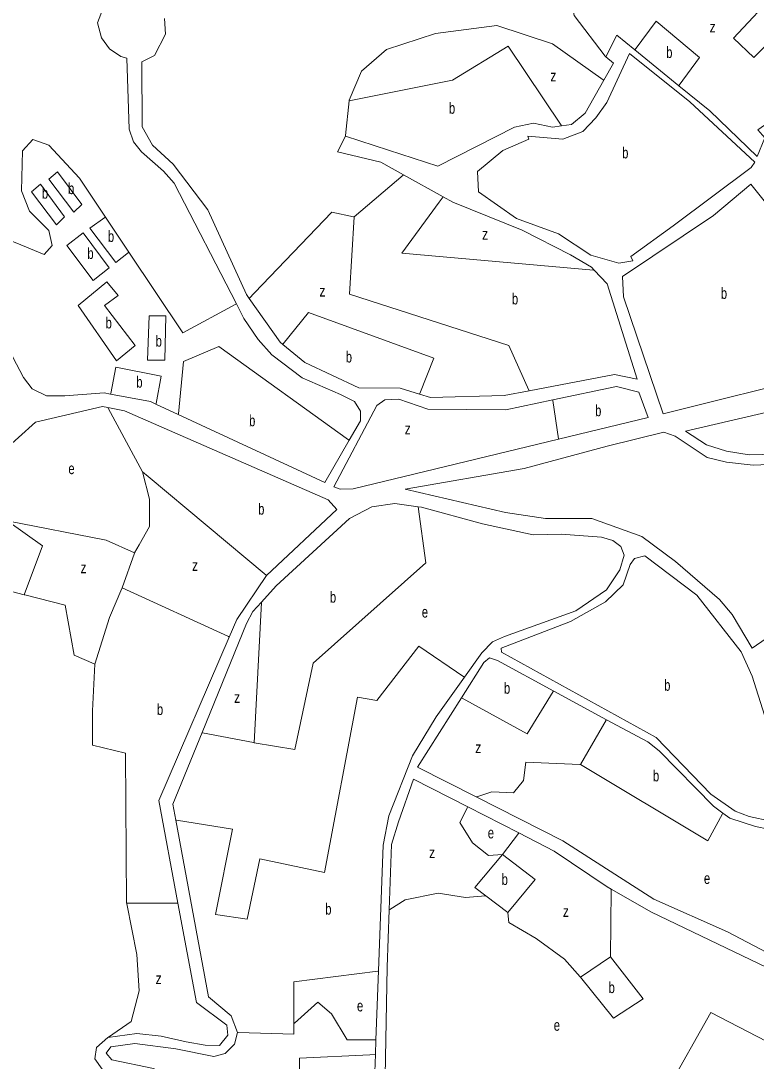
# Model space of a CAD drawing. Extents: x 639657 to 671642, y 222838 to 252123.
# Drawn here: x 644289 to 644946, y 240211 to 241140 of the extents above; entities that cross this region are included whole.
import ezdxf

# ---------------------------------------------------------------- set-up
doc = ezdxf.new("R2010")
doc.units = 0
doc.header["$LTSCALE"] = 4
doc.layers.add('1', color=7, linetype='Continuous', lineweight=13)
doc.layers.add('21', color=7, linetype='Continuous', lineweight=13)
doc.layers.add('7', color=7, linetype='Continuous')

msp = doc.modelspace()

# ---------------------------------------------------------------- linework, layer by layer
at = {"layer": '1'}
for p, q in [((644617.58, 241024.14), (644579.193, 241036.805)), ((644426.28, 240994.63), (644481.637, 240887.039)), ((644356.66, 240223.3), (644366.95, 240232.13))]:
    msp.add_line(p, q, dxfattribs=at)
for points in [[(644328.766, 241279.423), (644347.01, 241274.33), (644376.89, 241255.27), (644369.89, 241200.06), (644374.24, 241169.79), (644363.53, 241153.23), (644357.54, 241137.76), (644361.21, 241124.45), (644368.31, 241114.59), (644378.42, 241107.73), (644384, 241106.45), (644385.83, 241042.88), (644389.71, 241031.72), (644397.03, 241022.71), (644416.6, 241005.35), (644426.28, 240994.63)], [(644417.45, 241141.72), (644418.33, 241127.77), (644408.48, 241108.64), (644397.32, 241103.03), (644397.63, 241045.05), (644406.9, 241028.53), (644425.39, 241011.81), (644456.17, 240971.05), (644490.65, 240895.3), (644493.175, 240891.741)], [(644811.38, 241107.57), (644821.38, 241126.8), (644837.462, 241113.717), (644876.758, 241081.749)], [(644809.73, 241086.776), (644818.26, 241102), (644811.38, 241107.57)], [(644771.858, 241045.898), (644780.77, 241047.17), (644793.21, 241057.29), (644809.73, 241086.776)], [(644876.758, 241081.749), (644904.23, 241059.4), (644946.611, 241018.583), (644953.45, 241035.21), (644947.22, 241042.29), (644993.68, 241074.72)], [(644617.58, 241024.14), (644661.63, 241009.83), (644730.09, 241044.73), (644746.83, 241048.41), (644764.02, 241044.78), (644771.858, 241045.898)], [(644579.193, 241036.805), (644572.083, 241022.58), (644610.645, 241013.42)], [(644801.038, 240917.032), (644798.58, 240919.63), (644780.1, 240930.77), (644736.89, 240952.82), (644675, 240977.85), (644666.285, 240982.667), (644630.948, 241002.198), (644610.645, 241013.42)], [(644742.975, 240809.499), (644819.14, 240824.1), (644839.55, 240819.83), (644812.57, 240904.84), (644801.038, 240917.032)], [(644369.439, 240806.395), (644363.66, 240807.47), (644328.44, 240805.05), (644312.12, 240805.02), (644299.44, 240811.23), (644291.69, 240821.31), (644281.99, 240839.33), (644275.76, 240846.41), (644265.65, 240851.33), (644215.35, 240880.46), (644188.516, 240903.29)], [(644481.637, 240887.039), (644488.33, 240874.03), (644501.24, 240855.15), (644513.29, 240841.64), (644540.38, 240820.85), (644574.77, 240806.09), (644587.24, 240799.88), (644592.4, 240791.09), (644592.42, 240782.71), (644582.352, 240765.348)], [(644493.175, 240891.741), (644520.79, 240852.82), (644523.189, 240850.827)], [(644523.189, 240850.827), (644542.72, 240834.6), (644590.87, 240812.13), (644628.02, 240811.76), (644645.241, 240806.419)], [(644764.066, 240801.24), (644821.09, 240813.36), (644841.07, 240808.24), (644849.27, 240785.49), (644769.259, 240766.18)], [(644409.915, 240797.476), (644404.9, 240799.8), (644369.439, 240806.395)], [(644607.21, 240796.27), (644614.08, 240801.43), (644626.75, 240801.88), (644652.75, 240793.12), (644722.33, 240792.37), (644764.066, 240801.24)], [(644645.241, 240806.419), (644654.88, 240803.43), (644720.81, 240805.25), (644742.975, 240809.499)], [(644366.922, 240794.455), (644362.17, 240795.44), (644302.28, 240781.38), (644241.437, 240726.53)], [(644508.67, 240644.48), (644571.5, 240703.43), (644563.75, 240712.22), (644381.72, 240791.39), (644366.922, 240794.455)], [(644582.352, 240765.348), (644560.51, 240727.68), (644429.845, 240788.239), (644409.915, 240797.476)], [(644769.259, 240766.18), (644585.86, 240721.92), (644574.48, 240721.47), (644568.67, 240723.83), (644607.21, 240796.27)], [(645121.99, 240708.78), (645115.27, 240725.93), (645093.96, 240740.23), (645047.48, 240754.87), (644939.52, 240752.35), (644919.12, 240755.53), (644901.5, 240761.09), (644882.79, 240773.52), (644963.16, 240792.22)], [(645000.69, 240620.15), (644942.17, 240579.68), (644924.29, 240609.72), (644913.1, 240623.23), (644873.75, 240657.1), (644843.64, 240679.39), (644798.95, 240695.42), (644757.71, 240695.36), (644722.05, 240700.88), (644632.46, 240721.57), (644738.53, 240739.99), (644812.8, 240760.09), (644863.25, 240772.63), (644873.56, 240768.99), (644901.94, 240749.92), (644919.13, 240745.66), (644943.19, 240742.9), (645038.84, 240747.12)], [(644643.965, 240705.87), (644623.03, 240708.67), (644602.64, 240705.84), (644582.68, 240695.5), (644517.06, 240635.26), (644504.041, 240620.836)], [(644685.226, 240553.79), (644700.78, 240575.64), (644710.43, 240585.32), (644721.16, 240590.06), (644784.69, 240612.93), (644812.15, 240631.87), (644824.15, 240649.5), (644827.78, 240662.61), (644824.97, 240670.34), (644817.66, 240675.91), (644807.78, 240678.68), (644771.69, 240681.42), (644746.57, 240680.95), (644701.45, 240690.75), (644646.88, 240705.48), (644643.965, 240705.87)], [(644475.311, 240589.62), (644482.1, 240605.35), (644508.67, 240644.48)], [(644504.041, 240620.836), (644496.48, 240612.46), (644490.7, 240601.72), (644451.003, 240504.287)], [(644429.552, 240351.953), (644412.35, 240443.74), (644475.311, 240589.62)], [(644682.71, 240535.362), (644702.73, 240566.84), (644707.66, 240570.93), (644714.75, 240568.58), (644764.958, 240541.408), (644812.198, 240515.842)], [(644608.517, 240291.558), (644612.58, 240403.69), (644617.9, 240429.9), (644638.86, 240483.62), (644660.07, 240518.45), (644685.226, 240553.79)], [(644695.876, 240446.922), (644643.39, 240473.54), (644682.71, 240535.362)], [(644812.198, 240515.842), (644848.88, 240495.99), (644859.2, 240488.06), (644907.6, 240438.53), (644916.081, 240432.439)], [(644451.003, 240504.287), (644425.03, 240440.54), (644427.683, 240426.218), (644456.88, 240268.56)], [(644618.23, 240346.071), (644620.31, 240404.34), (644626.29, 240424.76), (644639.75, 240462.79), (644688.226, 240438.032), (644733.932, 240414.688)], [(645002.394, 240336.638), (645003.71, 240309.61), (645008.09, 240289.02), (645013.71, 240277.44), (644920.24, 240326.44), (644854.26, 240355.54), (644773, 240407.81), (644695.876, 240446.922)], [(644916.081, 240432.439), (644922.22, 240428.03), (644945, 240420.55), (644980.02, 240413.3), (644986.47, 240408.16), (644993.221, 240381.345), (644999.44, 240356.64)], [(644733.932, 240414.688), (644765.49, 240398.57), (644812.58, 240366.64), (644816.431, 240364.442)], [(644816.431, 240364.442), (644852.35, 240343.94), (644999.77, 240273.31)], [(644366.95, 240232.13), (644392.93, 240235.6), (644414.63, 240233.28), (644436.97, 240228.16), (644453.72, 240225.39), (644466.61, 240224.98), (644473.9, 240234.23), (644473.03, 240243.03), (644446.15, 240263.39), (644429.552, 240351.953)], [(644874.32, 239942.39), (644820.41, 239954.54), (644772.32, 239988.98), (644678.8, 240092.17), (644668.69, 240099.46), (644661.6, 240099.45), (644655.16, 240097.29), (644648.3, 240093.41), (644627.93, 240074.91), (644623.63, 240077.7), (644625.96, 240096.17), (644614.22, 240181.63), (644616.4, 240294.81), (644618.23, 240346.071)], [(644487.093, 240136.453), (644495.12, 240123.88), (644500.74, 240106.7), (644506.77, 240091.9), (644520.74, 240088.7), (644534.05, 240090.01), (644549.31, 240084.45), (644578.32, 240069.68), (644596.8, 240066.48), (644608.82, 240067.79), (644615.25, 240080.04), (644616.29, 240099.8), (644610.65, 240136.52), (644604.97, 240193.64), (644605.811, 240216.845), (644606.288, 240230.021), (644608.517, 240291.558)], [(644456.88, 240268.56), (644476.88, 240251.42), (644482.7, 240236.61)], [(644482.7, 240236.61), (644480.14, 240226.29), (644471.78, 240217.9), (644461.47, 240215.1), (644427.53, 240222.13), (644391.01, 240226.79), (644369.54, 240223.75), (644365.47, 240218.16), (644370.63, 240212.16), (644407.8, 240204.49), (644427.79, 240195.07), (644448, 240177.49), (644481.56, 240145.12), (644487.093, 240136.453)], [(644361.84, 240203.98), (644355.38, 240213.21), (644356.66, 240223.3)]]:
    msp.add_lwpolyline(points, dxfattribs=at)
for points in [[(644941.28, 241008.63), (644871.76, 240956.69), (644833.79, 240929.35), (644835.73, 240925.28), (644823.06, 240923.32), (644798.14, 240930.59), (644769.33, 240949.65), (644731.72, 240963.12), (644697.75, 240987.12), (644696.86, 241005.16), (644719.6, 241023.88), (644742.77, 241034.01), (644741.91, 241036.8), (644773.27, 241034.06), (644790.87, 241040.75), (644802.45, 241053.22), (644812.3, 241066.77), (644832.64, 241110.4), (644886.61, 241067.32), (644944.68, 241013.51)], [(645003.46, 240823.98), (645024.03, 240834), (644976.61, 240949.11), (644940.85, 240993.96), (644907.61, 240965.77), (644826.52, 240911.3), (644827.4, 240893.26), (644862.79, 240788.95)], [(644846.46, 240662.21), (644892.69, 240626.85), (644932.29, 240576.44), (644942.21, 240554.77), (644982.57, 240426.62), (644983.01, 240422.97), (644978.07, 240421.03), (644939.62, 240429.34), (644926.94, 240434.05), (644905.22, 240449.26), (644856.39, 240499.87), (644718.39, 240576.1), (644717.95, 240579.75), (644779.98, 240603.47), (644811.09, 240621.13), (644826.96, 240636.19), (644833.37, 240654.24), (644837.02, 240659.83)]]:
    msp.add_lwpolyline(points, close=True, dxfattribs=at)
at = {"layer": '21'}
for p, q in [((644344.855, 240950.411), (644368.211, 240919.256)), ((644350.893, 240954.551), (644373.943, 240923.803)), ((644815.572, 240304.002), (644788.919, 240285.907))]:
    msp.add_line(p, q, dxfattribs=at)
for points in [[(645012.85, 241169.32), (645012.35, 241169.607), (644957.006, 241201.414), (644905.209, 241161.786), (644836.146, 241200.398), (644819.896, 241180.076), (644804.662, 241183.124), (644785.365, 241183.124), (644778.256, 241172.963), (644783.334, 241144.512), (644811, 241108.07), (644811.38, 241107.57)], [(644250.13, 241164.834), (644232.864, 241132.318), (644217.63, 241096.755), (644211.536, 241080.497), (644226.77, 241071.352), (644225.755, 241025.628), (644216.614, 241024.612), (644223.723, 240952.468), (644236.926, 240955.517), (644261.301, 240950.436), (644285.676, 240941.291), (644310.052, 240931.13), (644317.161, 240939.259), (644314.114, 240952.468), (644296.848, 240969.742), (644289.739, 240988.032), (644290.755, 241023.596), (644299.895, 241033.757), (644314.114, 241028.676), (644341.536, 240999.209), (644364.861, 240964.333), (644385.719, 240933.147)], [(644582.24, 241068.304), (644582.451, 241068.804), (644593.412, 241094.723), (644615.755, 241114.029), (644659.427, 241128.254), (644714.271, 241135.367), (644764.037, 241119.11), (644809.23, 241087.13), (644809.73, 241086.776)], [(644837.462, 241113.717), (644837.831, 241114.217), (644856.459, 241139.432), (644895.053, 241106.916), (644877.121, 241082.249), (644876.758, 241081.749)], [(644582.24, 241068.304), (644674.662, 241086.594), (644724.427, 241117.077), (644771.525, 241046.398), (644771.858, 241045.898)], [(644579.193, 241036.805), (644579.241, 241037.305), (644582.24, 241068.304)], [(644586.809, 240964.662), (644630.448, 241001.773), (644630.948, 241002.198)], [(644666.285, 240982.667), (644662.641, 240977.667), (644629.465, 240932.147), (644800.537, 240917.076), (644801.038, 240917.032)], [(644586.809, 240964.662), (644586.309, 240964.765), (644567.005, 240968.727), (644497.97, 240896.741), (644493.175, 240891.741)], [(644350.893, 240954.551), (644364.361, 240963.983), (644364.861, 240964.333)], [(644742.975, 240809.499), (644742.751, 240809.999), (644724.934, 240849.843), (644582.747, 240895.567), (644586.809, 240964.662)], [(644344.855, 240950.411), (644330.364, 240939.259), (644353.723, 240907.76), (644368.211, 240919.256)], [(644373.943, 240923.803), (644385.219, 240932.75), (644385.719, 240933.147)], [(644385.719, 240933.147), (644433.958, 240861.019), (644481.137, 240886.766), (644481.637, 240887.039)], [(644523.189, 240850.827), (644523.593, 240851.327), (644546.184, 240879.31), (644657.903, 240838.666), (644645.437, 240806.919), (644645.241, 240806.419)], [(644582.352, 240765.348), (644581.852, 240765.707), (644465.95, 240848.827), (644434.465, 240835.617), (644429.894, 240788.739), (644429.845, 240788.239)], [(644369.439, 240806.395), (644369.534, 240806.895), (644374.036, 240830.536), (644414.661, 240822.408), (644410.01, 240797.976), (644409.915, 240797.476)], [(644764.066, 240801.24), (644764.14, 240800.74), (644769.185, 240766.68), (644769.259, 240766.18)], [(644397.903, 240737.055), (644367.192, 240793.956), (644366.922, 240794.455)], [(644390.793, 240664.912), (644394.856, 240672.025), (644403.996, 240688.283), (644403.996, 240712.669), (644397.903, 240737.055)], [(644397.903, 240737.055), (644402.903, 240732.876), (644508.17, 240644.903), (644508.67, 240644.48)], [(644643.965, 240705.87), (644643.977, 240705.782), (644650.793, 240655.768), (644550.246, 240566.351), (644533.996, 240489.127), (644497.434, 240495.224)], [(644277.043, 240693.363), (644277.543, 240693.008), (644308.527, 240671.009), (644292.277, 240627.317), (644254.901, 240637.179)], [(644277.043, 240693.363), (644365.403, 240676.089), (644390.793, 240664.912)], [(644379.621, 240633.413), (644390.616, 240664.412), (644390.793, 240664.912)], [(644379.621, 240633.413), (644379.41, 240632.913), (644368.449, 240606.995), (644355.246, 240565.334)], [(644475.311, 240589.62), (644474.59, 240589.95), (644379.621, 240633.413)], [(644355.246, 240565.334), (644354.746, 240565.556), (644336.965, 240573.463), (644328.84, 240618.172), (644292.777, 240627.192), (644292.277, 240627.317)], [(644497.434, 240495.224), (644504.015, 240620.337), (644504.041, 240620.836)], [(644427.683, 240426.218), (644428.182, 240426.137), (644478.137, 240418), (644462.902, 240341.792), (644491.34, 240337.728), (644502.512, 240391.581), (644560.403, 240379.388), (644589.856, 240535.868), (644607.121, 240532.819), (644644.7, 240581.592), (644684.726, 240554.133), (644685.226, 240553.79)], [(644355.246, 240565.334), (644353.215, 240523.674), (644353.215, 240493.191), (644382.668, 240486.078), (644383.684, 240351.953)], [(644764.958, 240541.408), (644764.646, 240540.908), (644741.184, 240503.352), (644683.21, 240535.088), (644682.71, 240535.362)], [(644812.198, 240515.842), (644811.906, 240515.342), (644788.919, 240475.918)], [(644497.434, 240495.224), (644496.934, 240495.322), (644451.503, 240504.189), (644451.003, 240504.287)], [(644695.876, 240446.922), (644696.377, 240447.089), (644709.7, 240451.531), (644728.997, 240450.515), (644738.137, 240461.692), (644740.168, 240477.95), (644788.419, 240475.939), (644788.919, 240475.918)], [(644788.919, 240475.918), (644902.669, 240407.839), (644915.808, 240431.939), (644916.081, 240432.439)], [(644719.332, 240395.58), (644706.653, 240394.63), (644692.434, 240405.807), (644681.262, 240424.097), (644687.976, 240437.532), (644688.226, 240438.032)], [(644719.332, 240395.58), (644733.55, 240414.188), (644733.932, 240414.688)], [(644719.332, 240395.58), (644694.465, 240366.179), (644704.519, 240358.549), (644723.918, 240343.825)], [(644723.918, 240343.825), (644748.293, 240373.291), (644719.332, 240395.58)], [(644815.572, 240304.002), (644816.418, 240363.533), (644816.431, 240364.442)], [(644704.519, 240358.549), (644704.018, 240358.507), (644686.34, 240357.034), (644661.965, 240361.098), (644632.512, 240355.002), (644618.73, 240346.384), (644618.23, 240346.071)], [(644383.684, 240351.953), (644383.784, 240351.453), (644392.824, 240306.229), (644394.856, 240273.713), (644387.746, 240246.279), (644367.45, 240232.47), (644366.95, 240232.13)], [(644383.684, 240351.953), (644429.052, 240351.953), (644429.552, 240351.953)], [(644788.919, 240285.907), (644788.482, 240286.407), (644774.7, 240302.164), (644749.309, 240320.454), (644724.934, 240334.68), (644723.974, 240343.325), (644723.918, 240343.825)], [(644788.919, 240285.907), (644818.372, 240249.327), (644844.778, 240266.601), (644815.572, 240304.002)], [(644532.981, 240244.585), (644532.981, 240281.842), (644608.018, 240291.494), (644608.517, 240291.558)], [(644532.981, 240244.585), (644533.481, 240245.03), (644554.309, 240263.553), (644566.496, 240253.392), (644580.715, 240230.021), (644605.788, 240230.021), (644606.288, 240230.021)], [(645054.47, 240177.13), (645053.97, 240177.389), (644905.208, 240254.407), (644865.598, 240184.296), (644913.333, 240157.878), (644896.067, 240127.395), (644950.911, 240099.96), (644943.801, 240085.734), (645027.083, 240044.074), (645034.192, 240060.332), (645102.052, 240024.264), (645102.552, 240023.998)], [(644482.7, 240236.61), (644483.2, 240236.595), (644532.981, 240235.102), (644532.981, 240244.585)], [(644605.811, 240216.845), (644600.811, 240216.618), (644538.059, 240213.764), (644538.059, 240183.281), (644492.093, 240141.047), (644487.093, 240136.453)]]:
    msp.add_lwpolyline(points, dxfattribs=at)
for points in [[(644994.487, 241102.948), (645012.865, 241123.174), (644965.131, 241166.866), (644925.521, 241124.19), (644943.803, 241106.916), (644967.162, 241130.287)], [(644322.006, 241004.962), (644343.567, 240975.839), (644336.458, 240968.726), (644314.114, 240998.193)], [(644306.772, 240993.785), (644328.333, 240964.662), (644321.224, 240957.549), (644298.88, 240987.016)], [(644374.575, 240836.061), (644391.302, 240849.842), (644363.88, 240885.406), (644376.067, 240894.551), (644365.911, 240906.744), (644340.52, 240885.406)], [(644403.711, 240876.261), (644418.724, 240876.261), (644417.708, 240836.633), (644402.474, 240836.633)]]:
    msp.add_lwpolyline(points, close=True, dxfattribs=at)

# ---------------------------------------------------------------- texts
at = {"layer": '7'}
for s, width, p in [('z', 0.8, (644904.192, 241129.27)), ('b', 0.75, (644865.389, 241106.524)), ('z', 0.8, (644762.005, 241085.578)), ('b', 0.75, (644671.404, 241056.735)), ('b', 0.75, (644826.069, 241016.86)), ('b', 0.75, (644331.38, 240984.984)), ('b', 0.75, (644308.02, 240980.919)), ('b', 0.75, (644366.927, 240942.307)), ('z', 0.8, (644701.067, 240944.34)), ('b', 0.75, (644348.645, 240927.066)), ('z', 0.8, (644555.833, 240893.535)), ('b', 0.75, (644727.632, 240886.51)), ('b', 0.75, (644914.187, 240891.455)), ('b', 0.75, (644364.895, 240865.084)), ('b', 0.75, (644409.583, 240848.826)), ('b', 0.75, (644579.351, 240834.689)), ('b', 0.75, (644392.317, 240812.247)), ('b', 0.75, (644801.945, 240786.721)), ('b', 0.75, (644493.023, 240777.787)), ('z', 0.8, (644632.005, 240770.587)), ('e', 0.75, (644331.681, 240735.035)), ('b', 0.75, (644501.1, 240698.849)), ('z', 0.8, (644342.552, 240646.621)), ('z', 0.8, (644442.083, 240648.653)), ('b', 0.75, (644565.132, 240620.292)), ('e', 0.75, (644647.238, 240606.995)), ('b', 0.75, (644863.581, 240541.62)), ('b', 0.75, (644720.523, 240539.004)), ('z', 0.8, (644479.661, 240530.786)), ('b', 0.75, (644410.709, 240520.016)), ('z', 0.8, (644694.973, 240486.078)), ('b', 0.75, (644853.57, 240460.764)), ('e', 0.75, (644706.145, 240409.871)), ('z', 0.8, (644653.752, 240392.247)), ('b', 0.75, (644718.491, 240368.299)), ('e', 0.75, (644899.114, 240369.227)), ('b', 0.75, (644560.996, 240341.85)), ('z', 0.8, (644773.177, 240339.759)), ('z', 0.8, (644409.583, 240279.808)), ('b', 0.75, (644813.96, 240271.769)), ('e', 0.75, (644589.347, 240255.424)), ('e', 0.75, (644765.051, 240238.15))]:
    msp.add_text(s, height=10, dxfattribs=dict(at, width=width)).set_placement(p)

doc.saveas('drawing.dxf')
